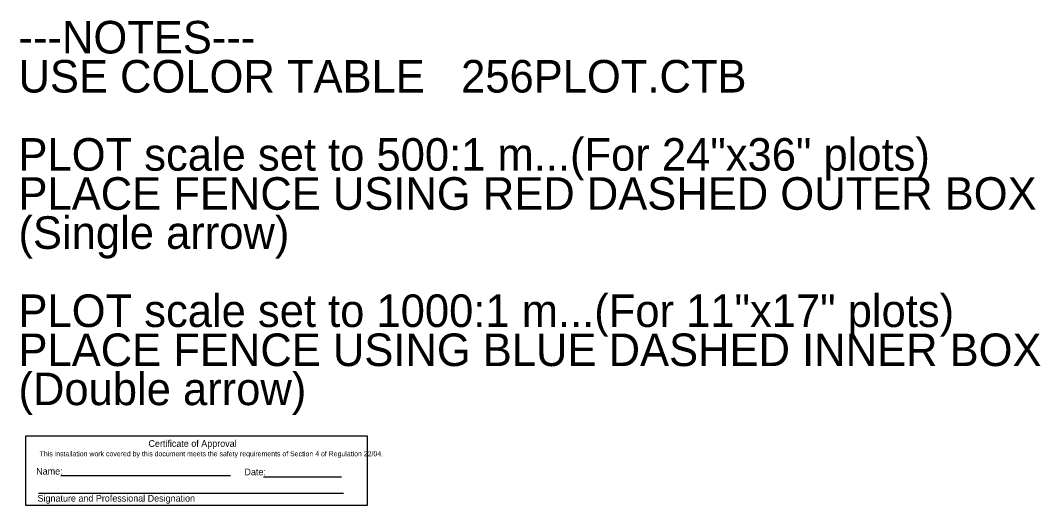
# Model space of a CAD drawing. Extents: x 602909 to 603631, y 4846273 to 4846729.
# Drawn here: x 603395.8 to 603630.8, y 4846394.2 to 4846505.9 of the extents above; entities that cross this region are included whole.
import ezdxf

# ---------------------------------------------------------------- set-up
doc = ezdxf.new("R2010")
doc.units = 0
for name, color, linetype in [('ENG_TITLEBLOCK', 7, 'Continuous'), ('ENG_TX_TITLEBLOCK', 7, 'Continuous'), ('ENG_WK_MISC-1', 7, 'Continuous')]:
    doc.layers.add(name, color=color, linetype=linetype)

msp = doc.modelspace()

# ---------------------------------------------------------------- linework, layer by layer
at = {"layer": 'ENG_TITLEBLOCK'}
for p, q in [((603405.06, 4846401.12), (603444.17, 4846401.12)), ((603451.8, 4846400.81), (603469.72, 4846400.81)), ((603399.91, 4846397.07), (603470.19, 4846397.07))]:
    msp.add_line(p, q, dxfattribs=at)
msp.add_lwpolyline([(603397.02, 4846410.25), (603475.65, 4846410.25), (603475.65, 4846394.19), (603397.02, 4846394.19)], close=True, dxfattribs=at)

# ---------------------------------------------------------------- texts
at = {"layer": 'ENG_TX_TITLEBLOCK'}
for s, height, p in [('Certificate of Approval', 1.5448, (603425.27, 4846407.72)), ('This installation work covered by this document meets the safety requirements of Section 4 of Regulation 22/04.', 1.15859, (603400.2, 4846405.55)), ('Name:', 1.545, (603399.4, 4846401.34)), ('Date:', 1.545, (603447.39, 4846401.18)), ('Signature and Professional Designation', 1.5448, (603399.71, 4846395.1))]:
    msp.add_text(s, height=height, rotation=360, dxfattribs=at).set_placement(p)
at = {"layer": 'ENG_WK_MISC-1'}
for s, p in [('---NOTES---', (603395.32, 4846498.33)), ('USE COLOR TABLE   256PLOT.CTB', (603395.32, 4846489.33)), ('PLOT scale set to 500:1 m...(For 24"x36" plots)', (603395.32, 4846471.33)), ('PLACE FENCE USING RED DASHED OUTER BOX', (603395.32, 4846462.33)), ('(Single arrow)', (603395.32, 4846453.33)), ('PLOT scale set to 1000:1 m...(For 11"x17" plots)', (603395.32, 4846435.33)), ('PLACE FENCE USING BLUE DASHED INNER BOX', (603395.32, 4846426.33)), ('(Double arrow)', (603395.32, 4846417.33))]:
    msp.add_text(s, height=7.5, dxfattribs=at).set_placement(p)

doc.saveas('drawing.dxf')
